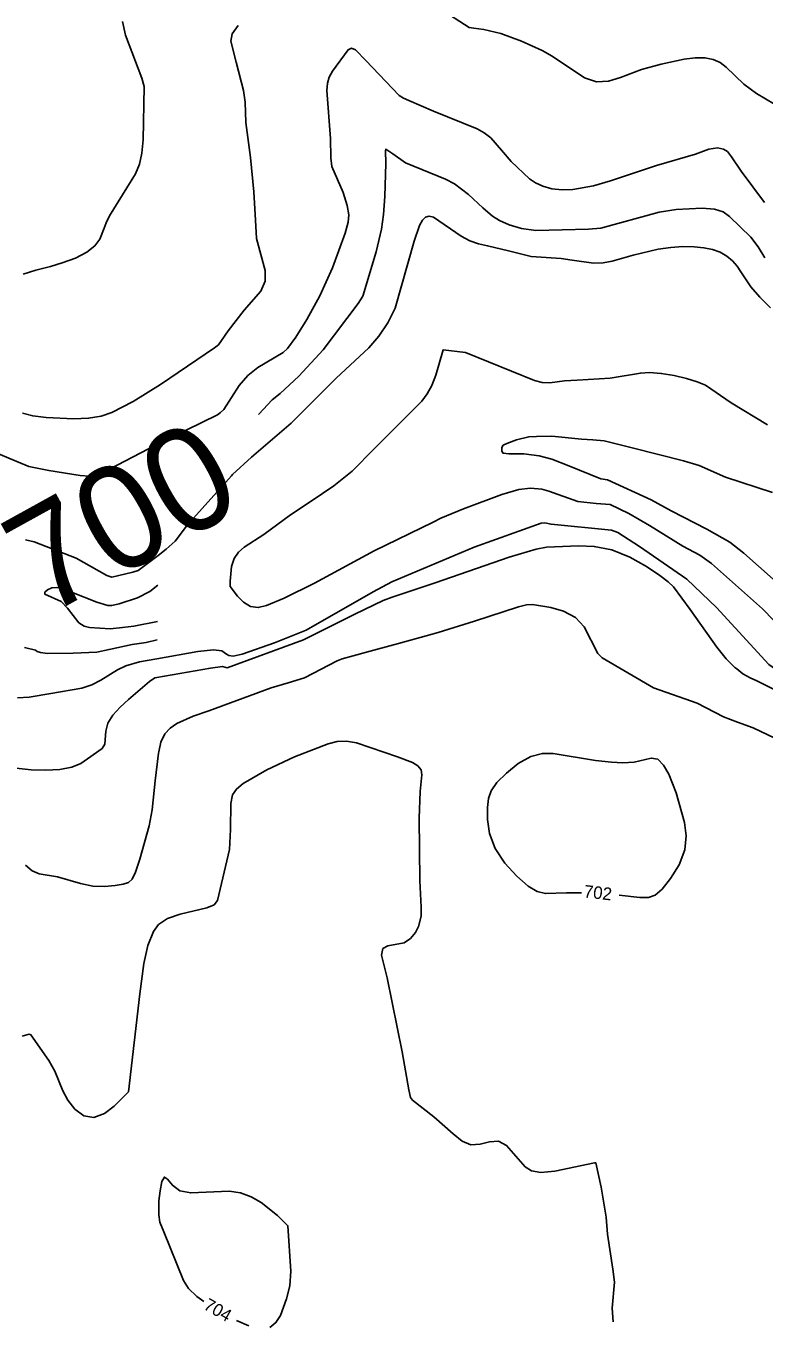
# Model space of a CAD drawing. Extents: x -291892836 to 2945206, y -477993085 to 1832792.
# Drawn here: x 1850778.6 to 1851013.6, y 544528.7 to 544942 of the extents above; entities that cross this region are included whole.
import ezdxf

# ---------------------------------------------------------------- set-up
doc = ezdxf.new("R2010")
doc.units = 0
for name, color, linetype in [('DT_X_Contour_Minor', 7, 'Continuous'), ('DT_X_Terrain_Ground_Line', 7, 'Continuous'), ('Level 19', 7, 'Continuous')]:
    doc.layers.add(name, color=color, linetype=linetype)

msp = doc.modelspace()

# ---------------------------------------------------------------- linework, layer by layer
at = {"layer": 'DT_X_Contour_Minor'}
for points in [[(1850910.54, 544947.42), (1850919.67, 544941.5), (1850921.24, 544941.22), (1850924.39, 544940.83), (1850929.8, 544939.53), (1850936.39, 544937.15), (1850942.96, 544934.11), (1850946.14, 544932.32), (1850956.44, 544925.42), (1850960.22, 544924.15), (1850964.12, 544924.37), (1850967.95, 544925.57), (1850974.65, 544928.14), (1850980.81, 544929.76), (1850988.17, 544931.35), (1850991.73, 544931.82), (1850994.79, 544931.83), (1850997.38, 544931.32), (1850999.6, 544930.31), (1851001.56, 544928.83), (1851007.14, 544923.4), (1851011.25, 544920.43), (1851016.93, 544917.07)], [(1850777.54, 544818.7), (1850780.74, 544817.83), (1850785.04, 544817.32), (1850793.85, 544816.87), (1850798.55, 544817.06), (1850802.51, 544817.75), (1850805.91, 544818.92), (1850812.68, 544822.44), (1850821.39, 544827.84), (1850838.65, 544839.47), (1850839.85, 544840.42), (1850843, 544844.89), (1850848.12, 544851.5), (1850853.39, 544857.56), (1850854.76, 544860.66), (1850854.71, 544864.1), (1850852.01, 544874.34), (1850851.66, 544880.08), (1850851.19, 544889.14), (1850850.1, 544900.09), (1850848.65, 544911.22), (1850848.4, 544917.67), (1850847.9, 544921.4), (1850845.51, 544930.44), (1850843.8, 544937.14), (1850844.26, 544939.41), (1850846.16, 544942.15)], [(1850777.74, 544862.92), (1850781.69, 544864.19), (1850786.37, 544865.33), (1850790.17, 544866.5), (1850794.33, 544868.08), (1850798.01, 544869.95), (1850800.57, 544871.99), (1850802.12, 544874.05), (1850803.51, 544877.54), (1850804.1, 544879.25), (1850805.2, 544881.51), (1850813.49, 544894.86), (1850814.74, 544897.93), (1850815.54, 544901.45), (1850815.95, 544905.73), (1850816.28, 544922.68), (1850815.51, 544925.33), (1850810.24, 544939.02), (1850809.28, 544943.41)], [(1850875.67, 544900.02), (1850875.58, 544906.08), (1850874.44, 544921.4), (1850874.57, 544923.75), (1850875.13, 544925.71), (1850876.18, 544927.62), (1850881.16, 544934.36), (1850882.28, 544934.86), (1850883.53, 544934.33), (1850886.86, 544930.92), (1850897.4, 544919.82), (1850898.85, 544918.96), (1850900.46, 544918.24), (1850908.38, 544914.81), (1850922.29, 544909.22), (1850924.52, 544907.95), (1850926.57, 544906.38), (1850930.05, 544902.45), (1850933.08, 544898.81), (1850938.91, 544893.24), (1850940.82, 544891.99), (1850943.23, 544890.91), (1850946.09, 544890.13), (1850949.29, 544889.75), (1850952.7, 544889.87), (1850959.28, 544891.04), (1850964.78, 544892.64), (1850979.37, 544897.55), (1850991.75, 544901.15), (1850996.03, 544902.73), (1850998.82, 544903.11), (1851000.69, 544902.75), (1851002.03, 544901.99), (1851003.26, 544900.26), (1851006.38, 544895.68), (1851013.78, 544885.8)], [(1850765.95, 544807.32), (1850779.48, 544801.76), (1850785.92, 544800.48), (1850795.84, 544798.83), (1850798.7, 544798.63), (1850800.87, 544798.87), (1850802.95, 544799.67), (1850819.87, 544808.45), (1850839.62, 544818.11), (1850840.59, 544818.85), (1850841.55, 544819.9), (1850846.52, 544827.54), (1850849.22, 544830.64), (1850852.43, 544833.18), (1850860.5, 544838), (1850861.91, 544839.28), (1850864.57, 544842.86), (1850868.05, 544848.52), (1850872.13, 544856.08), (1850876.17, 544864.97), (1850880.28, 544875.99), (1850881.24, 544879.54), (1850881.42, 544881.84), (1850880.92, 544884.81), (1850879.58, 544888.97), (1850876.01, 544897.17), (1850875.67, 544900.02)], [(1851013.84, 544868.12), (1851011.79, 544871.63), (1851009.38, 544874.7), (1851002.65, 544881.34), (1851000.64, 544882.74), (1850997.86, 544883.61), (1850993.93, 544883.91), (1850985.63, 544883.5), (1850980.24, 544882.72), (1850961.61, 544877.56), (1850957.69, 544877.27), (1850940.94, 544876.8), (1850936.34, 544877.5), (1850932.46, 544878.64), (1850929.38, 544879.99), (1850927.13, 544881.38), (1850924.09, 544884.08), (1850919.5, 544888.28), (1850915.02, 544891.67), (1850912.19, 544893.21), (1850899.44, 544898.35), (1850895.42, 544901.22), (1850893.22, 544902.75), (1850893.13, 544902.27), (1850893.15, 544898.22), (1850892.87, 544887.71), (1850892.47, 544881.98), (1850891.84, 544877.29), (1850890.08, 544870.08), (1850885.85, 544855.97), (1850884.35, 544853.62), (1850873.23, 544838.8), (1850865.46, 544830.48), (1850859.5, 544824.93), (1850857, 544822.96), (1850852.79, 544818.38), (1850852.69, 544818.28)], [(1851015.67, 544852.21), (1851012.31, 544855.59), (1851009.45, 544858.87), (1851006.23, 544863.66), (1851005.04, 544865.48), (1851003.56, 544867.17), (1851001.73, 544868.68), (1850999.6, 544869.91), (1850997.19, 544870.79), (1850994.45, 544871.35), (1850991.32, 544871.64), (1850987.79, 544871.7), (1850983.95, 544871.48), (1850979.93, 544870.93), (1850971.97, 544868.97), (1850965.28, 544867.08), (1850962.37, 544866.56), (1850959.36, 544866.48), (1850952.5, 544867.45), (1850949.04, 544867.94), (1850939.45, 544868.54), (1850932.26, 544870.34), (1850925.61, 544871.97), (1850922.72, 544872.61), (1850919.95, 544873.58), (1850917.19, 544875.09), (1850908.39, 544881.09), (1850906.98, 544881.44), (1850905.81, 544881.12), (1850904.81, 544880.13), (1850903.92, 544878.47), (1850902.2, 544873.43), (1850896.11, 544852.13), (1850893.84, 544847.45), (1850891, 544843.22), (1850887.79, 544839.52), (1850877.34, 544829.8), (1850863.06, 544815.51), (1850850.42, 544804.65), (1850844.39, 544799.11), (1850844.05, 544798.73)], [(1851014.73, 544814.98), (1851003.12, 544821.93), (1850994.93, 544827.6), (1850992.31, 544828.66), (1850988.97, 544829.69), (1850985.01, 544830.64), (1850980.89, 544831.34), (1850977.18, 544831.65), (1850974.23, 544831.45), (1850964.67, 544829.84), (1850954.08, 544829.18), (1850950.11, 544828.93), (1850945.43, 544828.38), (1850942.93, 544828.46), (1850940.48, 544829.08), (1850918.56, 544837.95), (1850911.41, 544838.8), (1850911.23, 544838.16), (1850909.12, 544830.79), (1850907.86, 544827.54), (1850906.39, 544824.85), (1850904.65, 544822.55), (1850900.03, 544817.8), (1850889.59, 544807.42), (1850882.51, 544800.22), (1850876.59, 544795.6), (1850869.46, 544790.65), (1850862.81, 544786.32), (1850854.35, 544780.05), (1850848.07, 544776), (1850846.26, 544774.41), (1850844.88, 544772.4), (1850844.08, 544769.89), (1850843.61, 544765.24), (1850843.59, 544763.47), (1850845.95, 544760.39), (1850847.82, 544758.48), (1850850.06, 544757.11), (1850852.54, 544756.82), (1850855.19, 544757.41), (1850860.8, 544759.78), (1850870.51, 544764.58), (1850889.52, 544774.83), (1850908.26, 544783.98), (1850910.74, 544785.29), (1850917.94, 544788.28), (1850930.12, 544792.8), (1850935.49, 544794.42), (1850939.27, 544794.79), (1850942.9, 544794.44), (1850945.06, 544793.88), (1850954.33, 544790.6), (1850960.19, 544789.93), (1850964.59, 544789.56), (1850970.55, 544786.78), (1850977.16, 544782.97), (1850987.79, 544776.39), (1850993.15, 544773.53), (1850996.86, 544770.85), (1851013.09, 544756.35), (1851020.47, 544748.88)], [(1851016.31, 544793.39), (1851001.36, 544798.27), (1850992.94, 544802.05), (1850987.97, 544803.56), (1850971.58, 544807.69), (1850962.66, 544809.86), (1850959.11, 544810.23), (1850955.45, 544810.41), (1850946.06, 544811.38), (1850941.16, 544811.26), (1850938.71, 544811.16), (1850934.78, 544810.16), (1850931.68, 544809.08), (1850930.6, 544808.45), (1850930.1, 544807.79), (1850930.14, 544806.6), (1850930.54, 544805.92), (1850932.35, 544805.75), (1850937.16, 544805.71), (1850942.02, 544805.09), (1850946.07, 544804.03), (1850951.45, 544801.95), (1850961.68, 544797.74), (1850963.77, 544797.45), (1850977.69, 544791.11), (1850984.09, 544787.63), (1850995.38, 544781.74), (1851002.75, 544777.66), (1851007.14, 544774.08), (1851022.17, 544760.86)], [(1850844.05, 544798.73), (1850830, 544783.16), (1850826.1, 544777.96), (1850823.26, 544775.39), (1850820.67, 544773.41)], [(1850820.29, 544740.48), (1850833.36, 544742.8), (1850838.29, 544743.33), (1850840.93, 544742.98), (1850842.47, 544742.01), (1850843.15, 544741.51), (1850844.53, 544741.37), (1850847.4, 544741.98), (1850857.74, 544745.58), (1850867.85, 544749.63), (1850889.16, 544761.83), (1850895.09, 544765), (1850921.27, 544775.99), (1850942.61, 544783.7), (1850943.79, 544783.79), (1850945.83, 544783.31), (1850965.01, 544781.47), (1850967.05, 544780.69), (1850973.97, 544776.19), (1850989.04, 544765.86), (1850998.53, 544756.8), (1851015.12, 544738.68), (1851035.24, 544724.55), (1851038.29, 544722.84)], [(1850820.67, 544773.41), (1850814.37, 544768.58), (1850812.57, 544768.02), (1850805.92, 544766.53), (1850804.38, 544767.06), (1850801.93, 544768.35), (1850794.61, 544772.52), (1850781.25, 544777.72), (1850778.44, 544778.34)], [(1851004.93, 544737.26), (1851004.34, 544737.73), (1851001.57, 544740.53), (1850998.57, 544744.21), (1850990.12, 544756.19), (1850984.83, 544763.37), (1850983.13, 544764.96), (1850980.41, 544766.99), (1850976.18, 544769.82), (1850970.87, 544772.84), (1850965.12, 544775.21), (1850959.54, 544776.29), (1850954.51, 544776.44), (1850944.31, 544775.98), (1850941.1, 544775.43), (1850932.45, 544772.84), (1850908.94, 544764.62), (1850895.19, 544760.1), (1850892.37, 544759.06), (1850883.33, 544754.67), (1850866.97, 544746.49), (1850842.69, 544737.66), (1850841.21, 544738.08), (1850837.33, 544737.49), (1850820.23, 544734.5)], [(1850820.56, 544763.93), (1850818.05, 544761.94), (1850814.09, 544759.93), (1850808.22, 544757.99), (1850805.91, 544757.45), (1850804.67, 544757.48), (1850801.18, 544758.5), (1850789.56, 544763.13), (1850788.25, 544763.24), (1850786.83, 544763.07), (1850785.49, 544762.49), (1850784.61, 544761.72), (1850784.6, 544761.04), (1850789.79, 544758.78), (1850791.79, 544756.63), (1850795.39, 544751.98), (1850797.15, 544750.83), (1850798.86, 544750.42), (1850805.42, 544750.07), (1850809.29, 544750.49), (1850812.9, 544750.85), (1850820.43, 544752.39)], [(1851017.02, 544715.21), (1851010.15, 544718.47), (1851005.21, 544720.33), (1851000.7, 544722.01), (1850992.34, 544726.33), (1850978.38, 544731.28), (1850962.04, 544740.76), (1850960.74, 544742.21), (1850956.37, 544750.67), (1850953.58, 544753.65), (1850949.8, 544755.67), (1850945.72, 544756.84), (1850939.92, 544757.77), (1850938.01, 544757.68), (1850935.39, 544757.04), (1850921.4, 544752.49), (1850909.87, 544748.82), (1850897.23, 544745.35), (1850890.54, 544743.53)], [(1850778.14, 544744.12), (1850781.61, 544743.23), (1850782.11, 544742.86), (1850783.17, 544742.47), (1850785.42, 544742.2), (1850793.62, 544742.31), (1850801.17, 544742.65), (1850805.07, 544743.5), (1850812.46, 544745.06), (1850816.87, 544745.73), (1850820.36, 544746.5)], [(1850890.54, 544743.53), (1850879.23, 544740.46), (1850877.64, 544739.83), (1850867.26, 544734.43), (1850862.05, 544732.82), (1850856.67, 544731.22), (1850836.82, 544723.96), (1850831.87, 544722.24), (1850826.61, 544719.86), (1850824.49, 544718.44), (1850822.82, 544716.59), (1850821.59, 544713.98), (1850820.85, 544710.82)], [(1850775.9, 544728.06), (1850779.61, 544728.31), (1850786.46, 544729.46), (1850796.43, 544731.19), (1850799.55, 544732.16), (1850802.4, 544733.64), (1850807.71, 544736.99), (1850810.34, 544738.2), (1850814.75, 544739.5), (1850820.29, 544740.48)], [(1850820.23, 544734.5), (1850819.58, 544734.38), (1850817.92, 544733.22), (1850811.24, 544727.51), (1850808.59, 544725.07), (1850806.27, 544722.56), (1850804.67, 544720), (1850804.03, 544717.46), (1850803.66, 544713.27), (1850802.84, 544711.96), (1850798.19, 544708.6), (1850796.06, 544707.19), (1850793.2, 544705.99), (1850789.4, 544705.26), (1850784.96, 544705), (1850780.3, 544705.13), (1850771.65, 544706.13)], [(1851063.69, 544702.75), (1851060.3, 544703.52), (1851052.93, 544704.63), (1851049.12, 544705.66), (1851045.38, 544707.43), (1851041.78, 544709.8), (1851038.4, 544712.53), (1851024.55, 544725.21), (1851020.39, 544728.37), (1851016.65, 544730.87), (1851011.37, 544733.44), (1851009.2, 544734.39), (1851006.88, 544735.74), (1851004.93, 544737.26)], [(1850965.63, 544529.35), (1850965.22, 544533.8), (1850965.95, 544542.08), (1850965.48, 544546.13), (1850963.75, 544557.3), (1850963.4, 544562.74), (1850961.79, 544572.25), (1850960.06, 544580.02), (1850959.59, 544579.99), (1850947.05, 544577.4), (1850942.59, 544576.98), (1850939.54, 544577.46), (1850937.51, 544578.79), (1850931.63, 544585.58), (1850929.05, 544586.87), (1850926.21, 544586.73), (1850923.23, 544585.99), (1850920.28, 544585.78), (1850917.45, 544586.97), (1850914.64, 544589.24), (1850908.46, 544594.69), (1850901.67, 544599.99), (1850901.06, 544600.82), (1850900.55, 544603.31), (1850898.39, 544615.31), (1850893.64, 544638.89), (1850891.84, 544646.17), (1850892.18, 544648.24), (1850893.87, 544649.15), (1850899, 544650.1), (1850901.08, 544651.45), (1850902.58, 544653.33), (1850903.58, 544655.31), (1850904.44, 544658.57), (1850904.41, 544661.41), (1850904.01, 544669.87), (1850903.8, 544689.74), (1850904.1, 544698.25), (1850904.68, 544703.58), (1850904.42, 544705.18), (1850903.39, 544706.41), (1850901.69, 544707.43), (1850896.88, 544709.28), (1850883.89, 544713.71), (1850880.63, 544714.31), (1850877.7, 544714.18), (1850874.85, 544713.46), (1850864.1, 544709.32), (1850855.28, 544705.15), (1850847.79, 544700.76), (1850845.61, 544699.03), (1850844.41, 544697.14), (1850843.88, 544694.43), (1850843.71, 544686.16), (1850843.44, 544679.75), (1850839.63, 544663.53), (1850838.49, 544662.14), (1850836.18, 544661.18), (1850827.74, 544659.24), (1850823.63, 544657.82), (1850820.84, 544655.91), (1850819.18, 544653.68), (1850817.4, 544649.17), (1850816.13, 544643.49), (1850814.83, 544633.83), (1850811.19, 544602.58), (1850810.97, 544602.3), (1850806.69, 544598.08), (1850803.61, 544595.71), (1850800.25, 544594.41), (1850797.01, 544595.03), (1850794.16, 544597.14), (1850791.91, 544599.98), (1850790.38, 544602.95), (1850787.76, 544609.21), (1850785.83, 544612.6), (1850780.16, 544620.76), (1850779.63, 544620.96), (1850777.35, 544620.36)], [(1850820.85, 544710.82), (1850820.75, 544710.41), (1850819.77, 544701.59), (1850818.74, 544692.36), (1850817.79, 544687.31), (1850814.86, 544676.66), (1850813.44, 544672.61), (1850812.36, 544670.29), (1850811.24, 544669.25), (1850809.57, 544668.76), (1850806.96, 544668.28), (1850803.62, 544667.96), (1850799.86, 544668.11), (1850795.98, 544668.93), (1850788.67, 544671.07), (1850782.84, 544672.06), (1850780.52, 544672.97), (1850778.49, 544674.74)], [(1850955.47, 544666.01), (1850950.74, 544665.95), (1850944.01, 544665.75), (1850941.42, 544666.41), (1850938.51, 544668.15), (1850934.86, 544671.26), (1850931.06, 544675.4), (1850927.98, 544680.1), (1850926.23, 544684.87), (1850925.57, 544689.34), (1850925.54, 544693.14), (1850925.83, 544696.04), (1850926.69, 544698.49), (1850928.52, 544701.06), (1850931.56, 544704.11), (1850935.37, 544707.13), (1850939.37, 544709.38), (1850943.07, 544710.34), (1850946.5, 544710.3), (1850960, 544708.11), (1850965.09, 544707.57), (1850968.69, 544707.39), (1850972.28, 544707.6), (1850977.7, 544708.88), (1850979.78, 544708.51), (1850981.65, 544706.67), (1850983.3, 544703.81), (1850985.66, 544697.83), (1850988.31, 544688.35), (1850988.86, 544684.18), (1850988.4, 544679.63), (1850986.55, 544674.91), (1850983.87, 544670.55), (1850981.16, 544667.17), (1850978.97, 544665.22), (1850976.84, 544664.47), (1850974.07, 544664.53), (1850967.46, 544665.27)], [(1850835.23, 544535.91), (1850832.99, 544537.51), (1850830.38, 544540), (1850828.76, 544542.51), (1850822.52, 544558.08), (1850821.23, 544561.13), (1850820.85, 544563.51), (1850820.95, 544567.95), (1850821.31, 544571.14), (1850821.89, 544574.03), (1850822.68, 544575.49), (1850823.7, 544574.81), (1850825.24, 544572.9), (1850827.64, 544571.12), (1850831.08, 544570.46), (1850843.27, 544570.99), (1850846.87, 544570.45), (1850850.26, 544569.25), (1850853.51, 544567.38), (1850858.73, 544563.24), (1850861.98, 544560.01), (1850862.89, 544545.48), (1850862.66, 544540.88), (1850861.58, 544536.73), (1850859.61, 544531.47), (1850858.2, 544529.18), (1850856.23, 544527.62)], [(1850849.6, 544528.12), (1850845.59, 544529.87)]]:
    msp.add_lwpolyline(points, dxfattribs=at)

# ---------------------------------------------------------------- texts
at = {"layer": 'DT_X_Terrain_Ground_Line'}
msp.add_text('700', height=33, rotation=28.9229, dxfattribs=at).set_placement((1850784.54, 544753.48))
at = {"layer": 'Level 19'}
for s, rotation, p in [('702', 353.578, (1850956.08, 544664.54)), ('704', 330.293, (1850834.84, 544533.65))]:
    msp.add_text(s, height=4, rotation=rotation, dxfattribs=at).set_placement(p)

doc.saveas('drawing.dxf')
